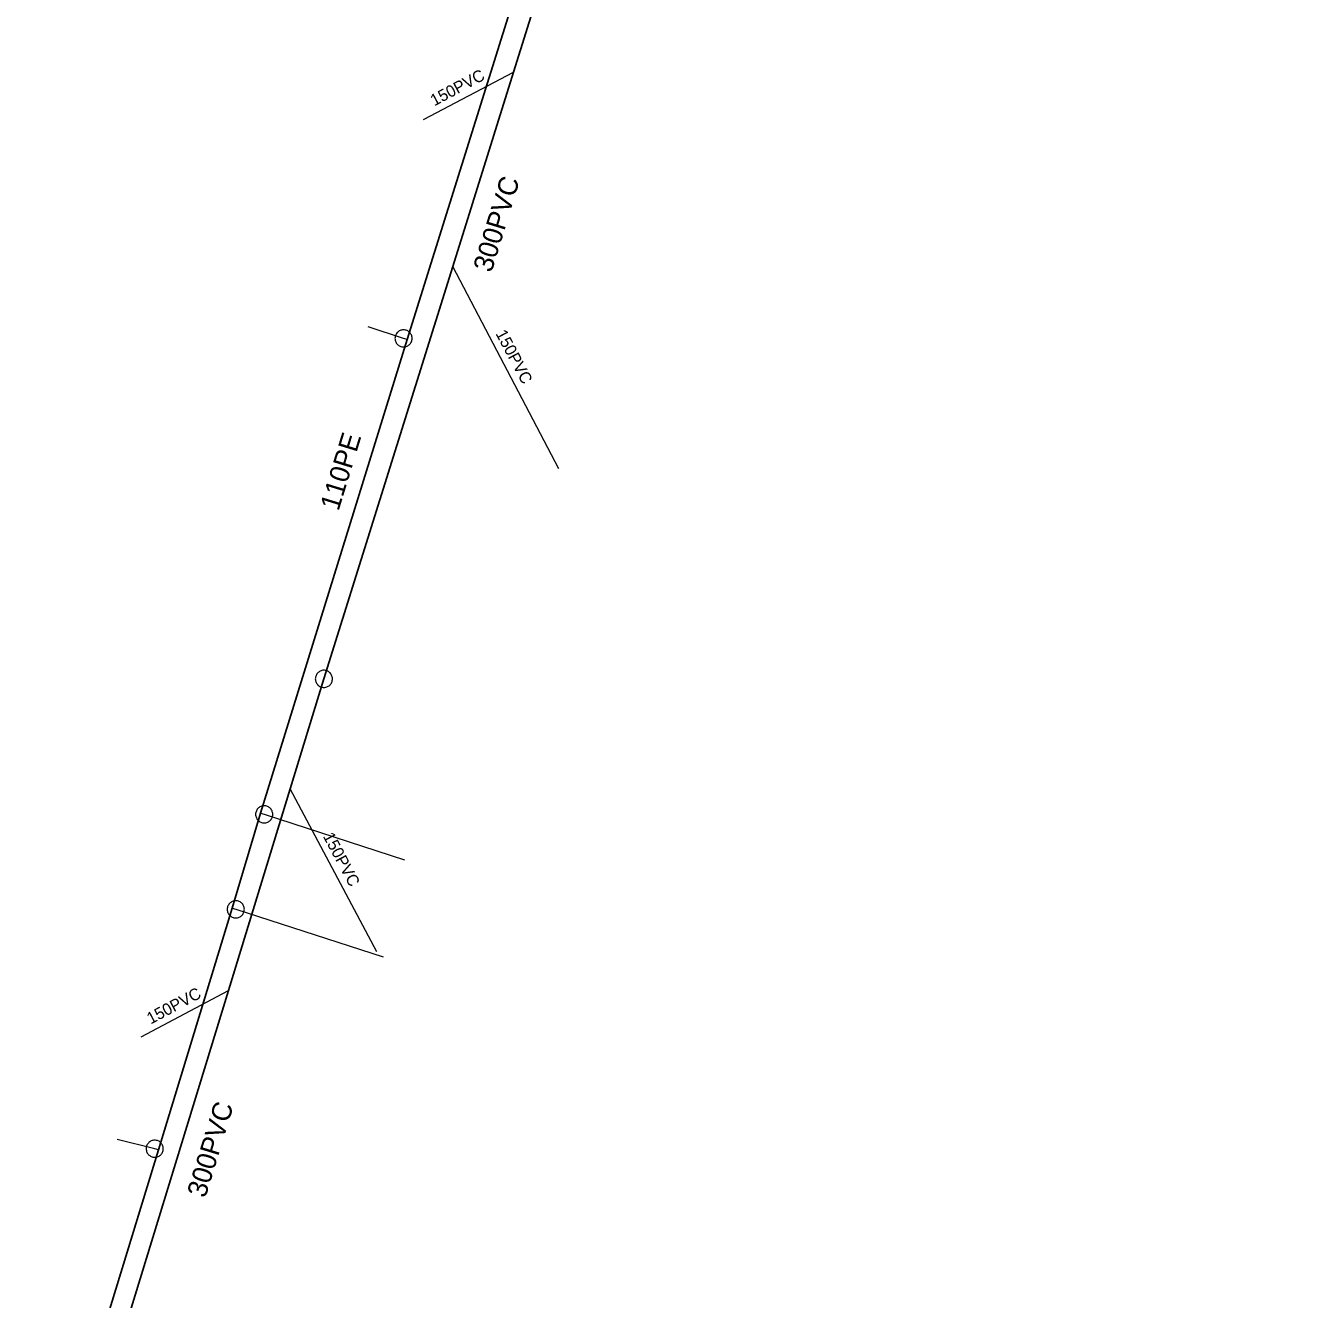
# Model space of a CAD drawing. Extents: x -741806 to -738704, y -1059275 to -1055387.
# Drawn here: x -740348.4 to -740282.6, y -1057368.6 to -1057303.6 of the extents above; entities that cross this region are included whole.
import ezdxf

# ---------------------------------------------------------------- set-up
doc = ezdxf.new("R2010")
doc.units = 0
doc.header["$LTSCALE"] = 0.4
for name, color, linetype, lineweight in [('2', 7, 'Continuous', 25), ('21', 7, 'Continuous', 13), ('3', 7, 'Continuous', 13), ('51', 7, 'Continuous', 13), ('52', 7, 'Continuous', 25), ('56', 7, 'Continuous', 13)]:
    doc.layers.add(name, color=color, linetype=linetype, lineweight=lineweight)
for name, color, linetype in [('5', 7, 'Continuous'), ('53', 7, 'Continuous'), ('55', 7, 'Continuous')]:
    doc.layers.add(name, color=color, linetype=linetype)

msp = doc.modelspace()

# ---------------------------------------------------------------- linework, layer by layer
at = {"layer": '2'}
for points in [[(-740333.19, -1057336.94), (-740326.603, -1057315.879), (-740323.499, -1057305.956), (-740318.07, -1057288.6)], [(-740347.34, -1057383.149), (-740338.066, -1057352.864), (-740334.91, -1057342.56), (-740333.19, -1057336.94)]]:
    msp.add_lwpolyline(points, dxfattribs=at)
at = {"layer": '21'}
for points in [[(-740328.93, -1057319.611), (-740329.12, -1057319.55), (-740330.932, -1057318.96)], [(-740336.432, -1057343.803), (-740336.239, -1057343.86), (-740329.077, -1057346.176)], [(-740337.881, -1057348.652), (-740337.69, -1057348.71), (-740330.158, -1057351.145)], [(-740341.638, -1057360.999), (-740341.829, -1057360.94), (-740343.752, -1057360.463)]]:
    msp.add_lwpolyline(points, dxfattribs=at)
at = {"layer": '3'}
msp.add_lwpolyline([(-740333.061, -1057336.521), (-740333.105, -1057336.511), (-740333.15, -1057336.504), (-740333.196, -1057336.502), (-740333.241, -1057336.505), (-740333.286, -1057336.513), (-740333.331, -1057336.526), (-740333.373, -1057336.543), (-740333.414, -1057336.564), (-740333.451, -1057336.591), (-740333.486, -1057336.62), (-740333.518, -1057336.653), (-740333.547, -1057336.689), (-740333.571, -1057336.728), (-740333.591, -1057336.768), (-740333.607, -1057336.812), (-740333.618, -1057336.856), (-740333.624, -1057336.902), (-740333.626, -1057336.947), (-740333.623, -1057336.993), (-740333.615, -1057337.038), (-740333.602, -1057337.082), (-740333.585, -1057337.124), (-740333.563, -1057337.165), (-740333.538, -1057337.203), (-740333.508, -1057337.238), (-740333.475, -1057337.269), (-740333.44, -1057337.298), (-740333.4, -1057337.323), (-740333.359, -1057337.342), (-740333.316, -1057337.358), (-740333.272, -1057337.369), (-740333.227, -1057337.376), (-740333.181, -1057337.377), (-740333.135, -1057337.374), (-740333.091, -1057337.366), (-740333.046, -1057337.354), (-740333.004, -1057337.336), (-740332.963, -1057337.314), (-740332.926, -1057337.289), (-740332.891, -1057337.26), (-740332.859, -1057337.227), (-740332.83, -1057337.191), (-740332.805, -1057337.152), (-740332.786, -1057337.111), (-740332.77, -1057337.068), (-740332.759, -1057337.023), (-740332.752, -1057336.978), (-740332.751, -1057336.933), (-740332.754, -1057336.887), (-740332.763, -1057336.841), (-740332.775, -1057336.798), (-740332.792, -1057336.755), (-740332.814, -1057336.715), (-740332.839, -1057336.677), (-740332.869, -1057336.641), (-740332.902, -1057336.609), (-740332.937, -1057336.582), (-740332.977, -1057336.557), (-740333.018, -1057336.537), (-740333.06, -1057336.521)], dxfattribs=at)
at = {"layer": '51'}
for points in [[(-740328.683, -1057319.55), (-740328.684, -1057319.505), (-740328.692, -1057319.46), (-740328.704, -1057319.415), (-740328.72, -1057319.373), (-740328.741, -1057319.332), (-740328.766, -1057319.293), (-740328.795, -1057319.258), (-740328.827, -1057319.225), (-740328.863, -1057319.197), (-740328.901, -1057319.172), (-740328.942, -1057319.151), (-740328.985, -1057319.134), (-740329.029, -1057319.122), (-740329.074, -1057319.115), (-740329.12, -1057319.113), (-740329.166, -1057319.115), (-740329.211, -1057319.122), (-740329.255, -1057319.134), (-740329.298, -1057319.151), (-740329.339, -1057319.172), (-740329.377, -1057319.197), (-740329.413, -1057319.225), (-740329.445, -1057319.258), (-740329.474, -1057319.293), (-740329.499, -1057319.332), (-740329.52, -1057319.373), (-740329.536, -1057319.415), (-740329.548, -1057319.46), (-740329.555, -1057319.505), (-740329.558, -1057319.551), (-740329.555, -1057319.596), (-740329.548, -1057319.641), (-740329.536, -1057319.686), (-740329.52, -1057319.728), (-740329.499, -1057319.769), (-740329.474, -1057319.808), (-740329.445, -1057319.843), (-740329.413, -1057319.876), (-740329.377, -1057319.904), (-740329.339, -1057319.929), (-740329.298, -1057319.95), (-740329.255, -1057319.967), (-740329.211, -1057319.978), (-740329.166, -1057319.986), (-740329.12, -1057319.988), (-740329.074, -1057319.986), (-740329.029, -1057319.978), (-740328.985, -1057319.967), (-740328.942, -1057319.95), (-740328.901, -1057319.929), (-740328.863, -1057319.904), (-740328.827, -1057319.876), (-740328.795, -1057319.843), (-740328.766, -1057319.808), (-740328.741, -1057319.769), (-740328.72, -1057319.728), (-740328.704, -1057319.686), (-740328.692, -1057319.641), (-740328.684, -1057319.596), (-740328.683, -1057319.551)], [(-740335.801, -1057343.86), (-740335.803, -1057343.815), (-740335.811, -1057343.77), (-740335.823, -1057343.725), (-740335.838, -1057343.683), (-740335.86, -1057343.642), (-740335.884, -1057343.603), (-740335.914, -1057343.568), (-740335.946, -1057343.535), (-740335.982, -1057343.507), (-740336.019, -1057343.482), (-740336.061, -1057343.461), (-740336.103, -1057343.444), (-740336.147, -1057343.432), (-740336.193, -1057343.425), (-740336.239, -1057343.423), (-740336.284, -1057343.425), (-740336.33, -1057343.432), (-740336.374, -1057343.444), (-740336.416, -1057343.461), (-740336.458, -1057343.482), (-740336.495, -1057343.507), (-740336.531, -1057343.535), (-740336.563, -1057343.568), (-740336.593, -1057343.603), (-740336.617, -1057343.642), (-740336.639, -1057343.683), (-740336.654, -1057343.725), (-740336.666, -1057343.77), (-740336.674, -1057343.815), (-740336.676, -1057343.861), (-740336.674, -1057343.906), (-740336.666, -1057343.951), (-740336.654, -1057343.996), (-740336.639, -1057344.038), (-740336.617, -1057344.079), (-740336.593, -1057344.118), (-740336.563, -1057344.153), (-740336.531, -1057344.186), (-740336.495, -1057344.214), (-740336.458, -1057344.239), (-740336.416, -1057344.26), (-740336.374, -1057344.277), (-740336.33, -1057344.288), (-740336.284, -1057344.296), (-740336.239, -1057344.298), (-740336.193, -1057344.296), (-740336.147, -1057344.288), (-740336.103, -1057344.277), (-740336.061, -1057344.26), (-740336.019, -1057344.239), (-740335.982, -1057344.214), (-740335.946, -1057344.186), (-740335.914, -1057344.153), (-740335.884, -1057344.118), (-740335.86, -1057344.079), (-740335.838, -1057344.038), (-740335.823, -1057343.996), (-740335.811, -1057343.951), (-740335.803, -1057343.906), (-740335.801, -1057343.861)], [(-740337.252, -1057348.71), (-740337.254, -1057348.665), (-740337.262, -1057348.62), (-740337.274, -1057348.575), (-740337.289, -1057348.533), (-740337.311, -1057348.492), (-740337.335, -1057348.453), (-740337.365, -1057348.418), (-740337.397, -1057348.385), (-740337.433, -1057348.357), (-740337.47, -1057348.332), (-740337.512, -1057348.311), (-740337.554, -1057348.294), (-740337.598, -1057348.282), (-740337.644, -1057348.275), (-740337.69, -1057348.273), (-740337.735, -1057348.275), (-740337.781, -1057348.282), (-740337.825, -1057348.294), (-740337.867, -1057348.311), (-740337.909, -1057348.332), (-740337.946, -1057348.357), (-740337.982, -1057348.385), (-740338.014, -1057348.418), (-740338.044, -1057348.453), (-740338.068, -1057348.492), (-740338.09, -1057348.533), (-740338.105, -1057348.575), (-740338.117, -1057348.62), (-740338.125, -1057348.665), (-740338.127, -1057348.711), (-740338.125, -1057348.756), (-740338.117, -1057348.801), (-740338.105, -1057348.846), (-740338.09, -1057348.888), (-740338.068, -1057348.929), (-740338.044, -1057348.968), (-740338.014, -1057349.003), (-740337.982, -1057349.036), (-740337.946, -1057349.064), (-740337.909, -1057349.089), (-740337.867, -1057349.11), (-740337.825, -1057349.127), (-740337.781, -1057349.138), (-740337.735, -1057349.146), (-740337.69, -1057349.148), (-740337.644, -1057349.146), (-740337.598, -1057349.138), (-740337.554, -1057349.127), (-740337.512, -1057349.11), (-740337.47, -1057349.089), (-740337.433, -1057349.064), (-740337.397, -1057349.036), (-740337.365, -1057349.003), (-740337.335, -1057348.968), (-740337.311, -1057348.929), (-740337.289, -1057348.888), (-740337.274, -1057348.846), (-740337.262, -1057348.801), (-740337.254, -1057348.756), (-740337.252, -1057348.711)], [(-740341.392, -1057360.94), (-740341.394, -1057360.895), (-740341.401, -1057360.85), (-740341.413, -1057360.805), (-740341.429, -1057360.763), (-740341.45, -1057360.722), (-740341.475, -1057360.683), (-740341.504, -1057360.648), (-740341.536, -1057360.615), (-740341.572, -1057360.587), (-740341.61, -1057360.562), (-740341.651, -1057360.541), (-740341.694, -1057360.524), (-740341.738, -1057360.512), (-740341.783, -1057360.505), (-740341.829, -1057360.503), (-740341.875, -1057360.505), (-740341.92, -1057360.512), (-740341.964, -1057360.524), (-740342.007, -1057360.541), (-740342.048, -1057360.562), (-740342.086, -1057360.587), (-740342.122, -1057360.615), (-740342.154, -1057360.648), (-740342.183, -1057360.683), (-740342.208, -1057360.722), (-740342.229, -1057360.763), (-740342.245, -1057360.805), (-740342.257, -1057360.85), (-740342.264, -1057360.895), (-740342.267, -1057360.941), (-740342.264, -1057360.986), (-740342.257, -1057361.031), (-740342.245, -1057361.076), (-740342.229, -1057361.118), (-740342.208, -1057361.159), (-740342.183, -1057361.198), (-740342.154, -1057361.233), (-740342.122, -1057361.266), (-740342.086, -1057361.294), (-740342.048, -1057361.319), (-740342.007, -1057361.34), (-740341.964, -1057361.357), (-740341.92, -1057361.368), (-740341.875, -1057361.376), (-740341.829, -1057361.378), (-740341.783, -1057361.376), (-740341.738, -1057361.368), (-740341.694, -1057361.357), (-740341.651, -1057361.34), (-740341.61, -1057361.319), (-740341.572, -1057361.294), (-740341.536, -1057361.266), (-740341.504, -1057361.233), (-740341.475, -1057361.198), (-740341.45, -1057361.159), (-740341.429, -1057361.118), (-740341.413, -1057361.076), (-740341.401, -1057361.031), (-740341.394, -1057360.986), (-740341.392, -1057360.941)]]:
    msp.add_lwpolyline(points, dxfattribs=at)
at = {"layer": '52'}
msp.add_lwpolyline([(-740249.71, -1057396.29), (-740253.596, -1057395.887), (-740273.502, -1057395.585), (-740279.574, -1057395.223), (-740280.318, -1057395.179), (-740284.998, -1057395.12), (-740299.727, -1057394.348), (-740308.203, -1057393.86), (-740318.232, -1057393.49), (-740336.401, -1057392.97), (-740344.776, -1057392.614), (-740348.414, -1057383.139), (-740347.592, -1057380.453), (-740341.638, -1057360.999), (-740337.881, -1057348.652), (-740336.432, -1057343.803), (-740328.93, -1057319.611), (-740321.949, -1057297.29), (-740319.561, -1057289.659), (-740319.489, -1057289.497)], dxfattribs=at)
at = {"layer": '56'}
for p, q in [((-740328.109, -1057308.37), (-740323.499, -1057305.956)), ((-740321.19, -1057326.22), (-740326.603, -1057315.879)), ((-740330.491, -1057350.879), (-740334.91, -1057342.56)), ((-740342.52, -1057355.23), (-740338.066, -1057352.864))]:
    msp.add_line(p, q, dxfattribs=at)

# ---------------------------------------------------------------- texts
at = {"layer": '5'}
for p in [(-740324.63, -1057316.225), (-740339.244, -1057363.493)]:
    msp.add_text('300PVC', height=1, rotation=73, dxfattribs=at).set_placement(p)
at = {"layer": '53'}
msp.add_text('110PE ', height=1, rotation=73, dxfattribs=at).set_placement((-740332.443, -1057328.402))
at = {"layer": '55'}
for rotation, p in [(28, (-740327.551, -1057307.704)), (298, (-740324.437, -1057319.301)), (298, (-740333.253, -1057344.974)), (28, (-740342.036, -1057354.599))]:
    msp.add_text('150PVC', height=0.6, rotation=rotation, dxfattribs=at).set_placement(p)

doc.saveas('drawing.dxf')
